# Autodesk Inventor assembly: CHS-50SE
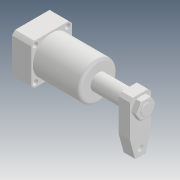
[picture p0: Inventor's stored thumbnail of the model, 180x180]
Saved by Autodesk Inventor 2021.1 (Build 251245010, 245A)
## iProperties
Created: 2019-04
Part Number: CHS-50SE
Description: STEP AP203
Document SubType Name: Assembly
Designer: user
Title: chs-50se_asm.STEP
Revision Number: ÈÎºÎ
Sending System: SolidWorks 2017
Preprocessor: SwSTEP 2.0
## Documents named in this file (5)
- D:\Vault_2016\Projekty\Clamptek\Hydraulic\CHS\CHS-50\Inventor\CHS-50SE\CHS-50SE.iam
- D:\Vault_2016\Projekty\Clamptek\Hydraulic\CHS\CHS-50\Inventor\CHS-50SE\CHS-50-EBT_1.ipt
- D:\Vault_2016\Projekty\Clamptek\Hydraulic\CHS\CHS-50\Inventor\CHS-50SE\CHS-50-ESHSG.ipt
- D:\Vault_2016\Projekty\Clamptek\Hydraulic\CHS\CHS-50\Inventor\CHS-50SE\CHS-50SYB_1.ipt
- D:\Vault_2016\Projekty\Clamptek\Hydraulic\CHS\CHS-50\Inventor\CHS-50SE\M20LM_1.ipt
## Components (4 placed, 4 different names)
1. CHS-50-EBT_1_1
2. CHS-50-ESHSG_2
3. CHS-50SYB_1_3
4. M20LM_1_4
